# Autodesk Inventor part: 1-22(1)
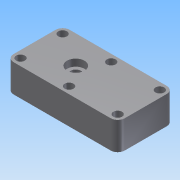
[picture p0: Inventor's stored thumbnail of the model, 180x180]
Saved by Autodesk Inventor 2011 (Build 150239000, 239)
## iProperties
Created: 2014-02
Part Number: 1-22(1)
Document SubType Name: Modeling
Designer: Administrator
Density: 1 g/cm^3
Author: Administrator
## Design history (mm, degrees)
sketch "草图1"
  geometry: L1 (-15.917, 8.028)-(15.917, 8.028); L2 (15.917, 8.028)-(15.917, -8.028); L3 (15.917, -8.028)-(-15.917, -8.028); L4 (-15.917, -8.028)-(-15.917, 8.028); 3 further points
  constraints: 8 end point, 2 midpoint, 2 parallel, 1 horizontal, 1 horizontal alignment, 1 perpendicular, 1 vertical alignment
extrude "拉伸1" new body sketch "草图1" distance "d0" = 8; taper "d1" = 0 deg
fillet "圆角1" dims "d2" = 2
sketch "草图2"
  geometry: L1 (7.97, -3)-(-7.97, -3); L2 (-7.97, -3)-(-7.97, 3); L3 (-7.97, 3)-(7.97, 3); L4 (7.97, 3)-(7.97, -3); 5 further points
  constraints: 8 end point, 2 horizontal alignment, 2 midpoint, 2 parallel, 2 vertical alignment, 1 horizontal, 1 perpendicular
  dimensions: "d35" = 6 distance of L3.end L1.start
extrude "拉伸2" cut sketch "草图2" distance "d3" = 2; taper "d4" = 0 deg; distance "d24" = 3
sketch "草图3"
  geometry: L1 (-7.888, -2.851)-(-7.888, 2.851) reference; L2 (6.888, -3.851)-(-6.888, -3.851) reference; L3 (-6.888, 3.851)-(6.888, 3.851) reference; L4 (7.888, 2.851)-(7.888, -2.851) reference; C1 r 1.5 at (-4.127, 0); 1 further point
  constraints: 1 centre point
  dimensions: "d6" = 3 diameter of C1
extrude "拉伸3" cut sketch "草图3" stored distance "d7" = 2; taper "d8" = 0 deg
hole "Hole1" diameter "d11" = 5; stored, may be unused: countersink angle "d15" = 90 deg, drill point angle "d17" = 0 deg; dims "d9" = 10, "d10" = 10, "d12" = 6, "d13" = 4, "d14" = 2, "d16" = 2
sketch "草图4"
  geometry: C1 r 1.25 at (13.917, -6.028); C2 r 1.25 at (0, -6.028); C3 r 1.25 at (-13.917, -6.028); C4 r 1.25 at (-13.917, 6.028); C5 r 1.25 at (0, 6.028); C6 r 1.25 at (13.917, 6.028); A1 r 2 centre (-13.917, -6.028) between (-15.917, -6.028) and (-13.917, -8.028) reference; A2 r 2 centre (13.917, -6.028) between (13.917, -8.028) and (15.917, -6.028) reference; A3 r 2 centre (13.917, 6.028) between (15.917, 6.028) and (13.917, 8.028) reference; A4 r 2 centre (-13.917, 6.028) between (-13.917, 8.028) and (-15.917, 6.028) reference; 1 further point
  constraints: 6 centre point, 4 concentric, 2 horizontal alignment
  dimensions: "d18" = 2.5 diameter of C1; "d19" = 2.5 diameter of C2; "d20" = 2.5 diameter of C3; "d21" = 2.5 diameter of C4; "d22" = 2.5 diameter of C5; "d23" = 2.5 diameter of C6
extrude "拉伸4" cut sketch "草图4" distance "d24" = 3; taper "d25" = 0 deg
sketch "草图5"
  geometry: C1 r 1.25 at (0, 6.028) reference; C2 r 1.25 at (13.917, -6.028) reference; C3 r 1.25 at (0, -6.028) reference; C4 r 1.25 at (-13.917, -6.028) reference; C5 r 1.25 at (13.917, 6.028) reference; C6 r 1.25 at (-13.917, 6.028) reference; C7 r 1 at (-13.917, 6.028); C8 r 1 at (-13.917, -6.028); C9 r 1 at (0, -6.028); C10 r 1 at (0, 6.028); C11 r 1 at (13.917, -6.028); C12 r 1 at (13.917, 6.028); 1 further point
  constraints: 6 centre point, 6 coincident
  dimensions: "d26" = 2 diameter of C7; "d27" = 2 diameter of C8; "d28" = 2 diameter of C9; "d29" = 2 diameter of C10; "d30" = 2 diameter of C11; "d31" = 2 diameter of C12
extrude "拉伸5" cut sketch "草图5" stored distance "d32" = 3; taper "d33" = 0 deg
fillet "圆角3" dims "d34" = 1
node "实体1"
